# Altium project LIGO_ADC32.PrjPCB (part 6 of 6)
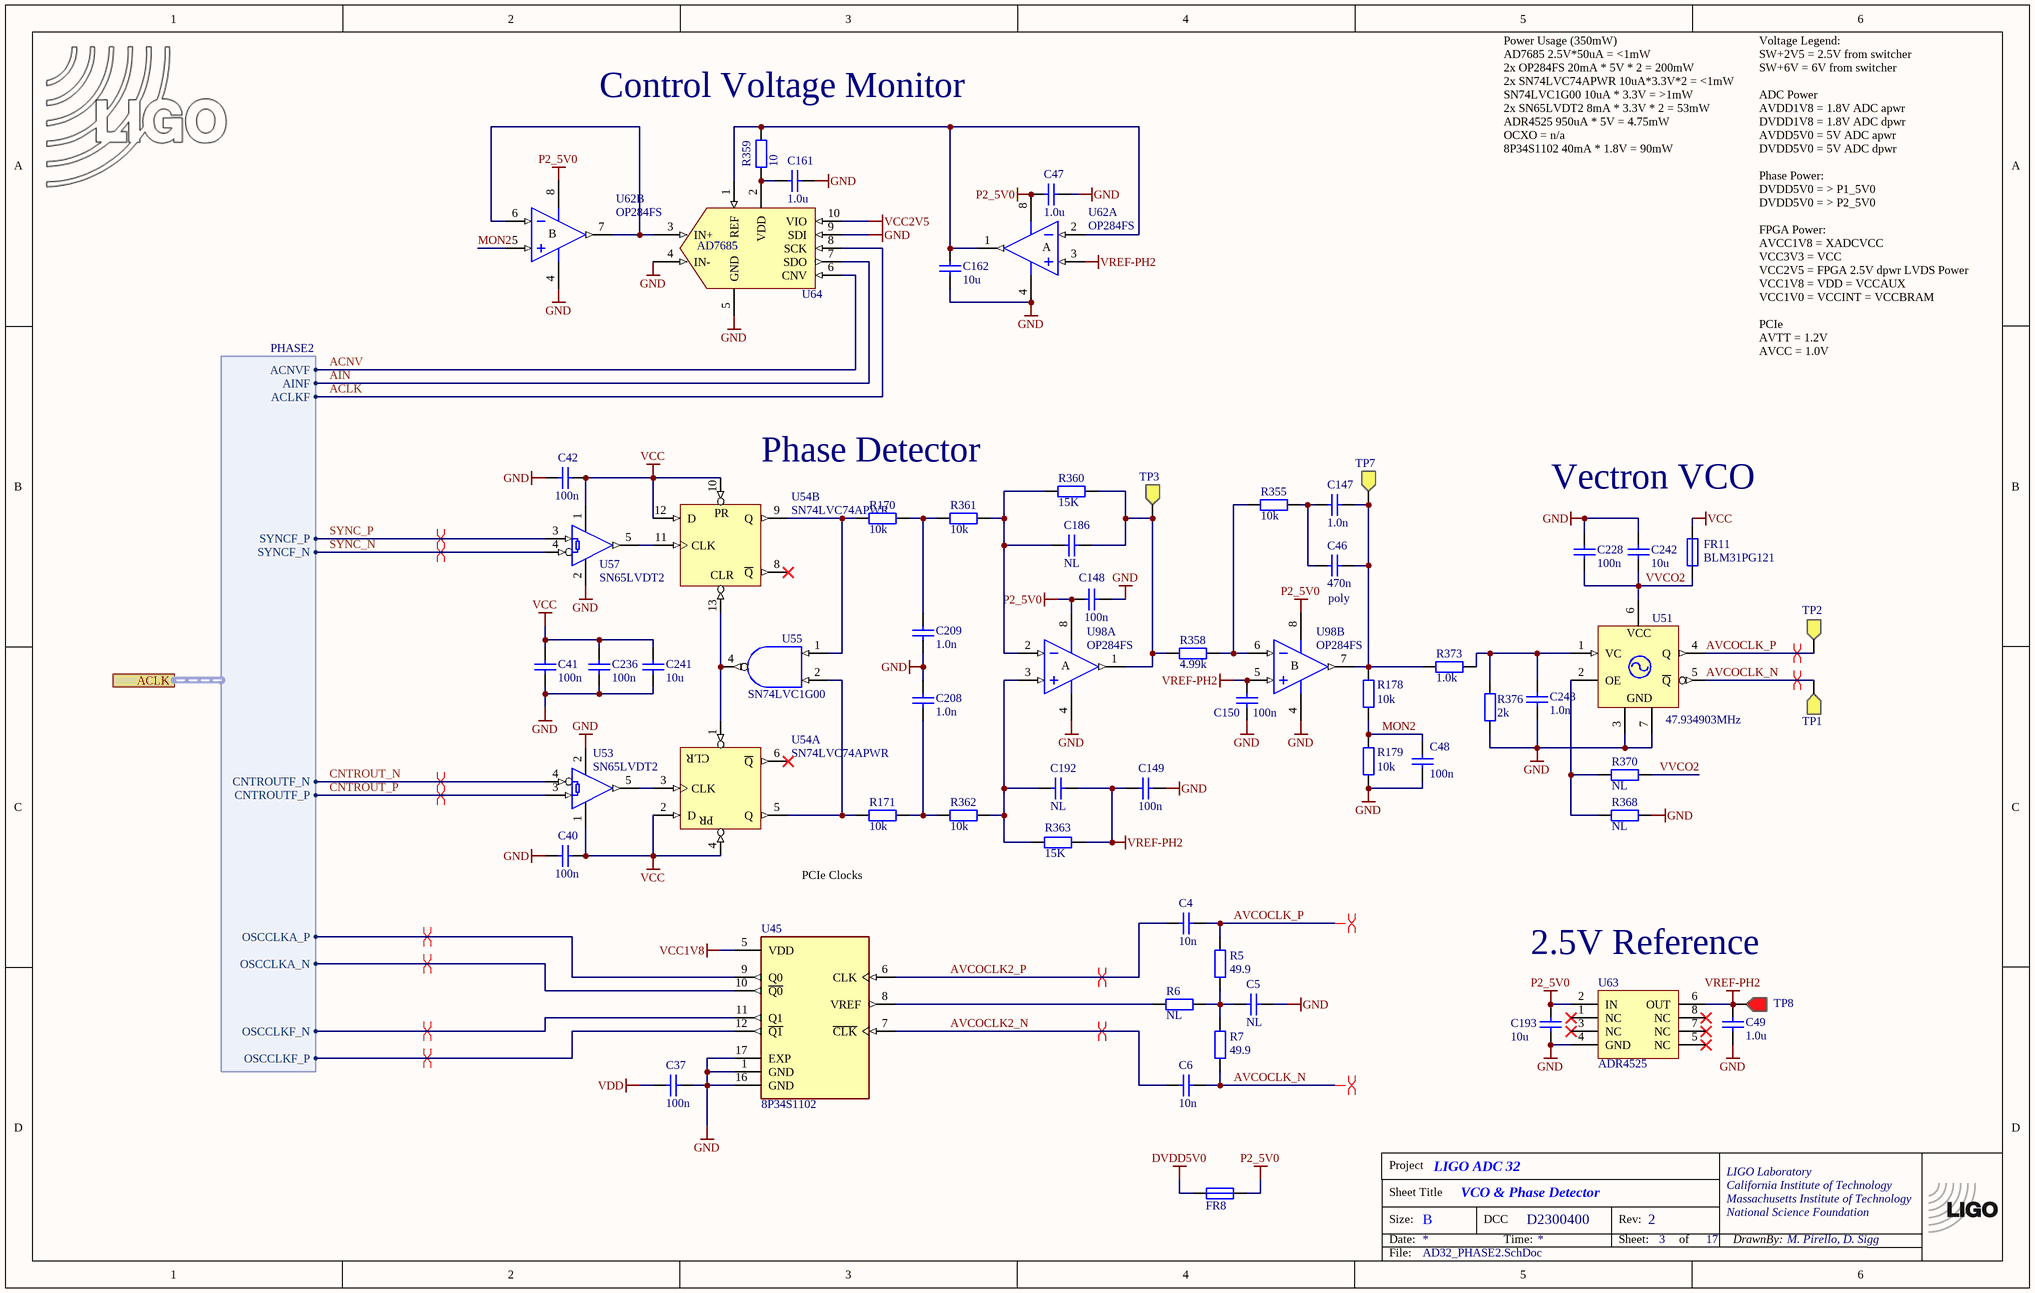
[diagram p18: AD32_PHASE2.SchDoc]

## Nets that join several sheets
12V: AD32_XADC (C110.1 R303.1 U94.8), AD32_PCIE_HL (5 pins)
12VA: AD32_PCIE_HL (FL2.2), AD32_Bipolar1 (FR5.1 TP39.1), AD32_Bipolar2 (FR6.1)
12VF: AD32_PCIE_HL (FL1.2), AD32_PowerFPGA (C111.1 R298.2)
+15V: Analog/ADC1/FrontEnd (20 pins), Analog/ADC2/FrontEnd (20 pins), Analog/ADC3/FrontEnd (20 pins), Analog/ADC4/FrontEnd (20 pins), Analog/ADC5/FrontEnd (20 pins), Analog/ADC6/FrontEnd (20 pins), Analog/ADC7/FrontEnd (20 pins), Analog/ADC8/FrontEnd (20 pins), AD32_XADC (C63.2 R202.1 U76.8), AD32_Bipolar1 (C129.2 D9.2 R327.1 TP17.1)
-15V: Analog/ADC1/FrontEnd (20 pins), Analog/ADC2/FrontEnd (20 pins), Analog/ADC3/FrontEnd (20 pins), Analog/ADC4/FrontEnd (20 pins), Analog/ADC5/FrontEnd (20 pins), Analog/ADC6/FrontEnd (20 pins), Analog/ADC7/FrontEnd (20 pins), Analog/ADC8/FrontEnd (20 pins), AD32_XADC (5 pins), AD32_Bipolar1 (C128.1 D10.1 R326.1 TP16.1)
AGND: ADC_TOP (12 pins), AD32_Inputs (10 pins), Analog/ADC1/FrontEnd (24 pins), Analog/ADC2/FrontEnd (24 pins), Analog/ADC3/FrontEnd (24 pins), Analog/ADC4/FrontEnd (24 pins), Analog/ADC5/FrontEnd (24 pins), Analog/ADC6/FrontEnd (24 pins), Analog/ADC7/FrontEnd (24 pins), Analog/ADC8/FrontEnd (24 pins), AD32_XADC (C63.1 C67.1 C145.1 U76.5), AD32_Power (20 pins), AD32_Bipolar1 (22 pins), AD32_Linear1 (35 pins), AD32_Bipolar2 (C108.1 C109.2 W2.2)
AVCC: FPGA_ARTIX7 (5 pins), AD32_PCIE_HL (11 pins)
AVCC1V8: AD32_XADC (C155.1 FR9.1), AD32_PowerFPGA (C64.2 R215.2 TP11.1 U77.7)
AVDD1V8: Analog/ADC1 (C289A.1 U34A.21), Analog/ADC2 (C289B.1 U34B.21), Analog/ADC3 (C289C.1 U34C.21), Analog/ADC4 (C289D.1 U34D.21), Analog/ADC5 (C289E.1 U34E.21), Analog/ADC6 (C289F.1 U34F.21), Analog/ADC7 (C289G.1 U34G.21), Analog/ADC8 (C289H.1 U34H.21), AD32_Linear1 (R223.1 R350.2 R351.1 TP21.1)
AVDD5V0: AD32_Inputs (C512.1 D2.2 R2.2 U133.8), Analog/ADC1 (C288A.1 C352A.1 C361A.1 U34A.26), Analog/ADC2 (C288B.1 C352B.1 C361B.1 U34B.26), Analog/ADC3 (C288C.1 C352C.1 C361C.1 U34C.26), Analog/ADC4 (C288D.1 C352D.1 C361D.1 U34D.26), Analog/ADC5 (C288E.1 C352E.1 C361E.1 U34E.26), Analog/ADC6 (C288F.1 C352F.1 C361F.1 U34F.26), Analog/ADC7 (C288G.1 C352G.1 C361G.1 U34G.26), Analog/ADC8 (C288H.1 C352H.1 C361H.1 U34H.26), AD32_Linear1 (6 pins)
AVTT: FPGA_ARTIX7 (7 pins), AD32_PCIE_HL (11 pins)
BUS3.3V: AD32_PCIE_HL (C287.1 R397.2 U99.6), AD32_PCIE (P2.A9 P2.A10 P2.B8)
BUS12V: AD32_PCIE_HL (D4.1), AD32_PCIE (5 pins)
DVDD1V8: Analog/ADC1 (5 pins), Analog/ADC2 (5 pins), Analog/ADC3 (5 pins), Analog/ADC4 (5 pins), Analog/ADC5 (5 pins), Analog/ADC6 (5 pins), Analog/ADC7 (5 pins), Analog/ADC8 (5 pins), AD32_Linear1 (R221.1 R348.2 R349.1 TP20.1)
DVDD5V0: Analog/ADC1 (C312A.1 C328A.1 C336A.1 U34A.25), Analog/ADC2 (C312B.1 C328B.1 C336B.1 U34B.25), Analog/ADC3 (C312C.1 C328C.1 C336C.1 U34C.25), Analog/ADC4 (C312D.1 C328D.1 C336D.1 U34D.25), Analog/ADC5 (C312E.1 C328E.1 C336E.1 U34E.25), Analog/ADC6 (C312F.1 C328F.1 C336F.1 U34F.25), Analog/ADC7 (C312G.1 C328G.1 C336G.1 U34G.25), Analog/ADC8 (C312H.1 C328H.1 C336H.1 U34H.25), AD32_PHASE (FR1.2), AD32_Linear1 (6 pins), AD32_PHASE2 (FR8.2)
EXTGND: AD32_PCIE_HL (6 pins), AD32_PCIE (21 pins)
GND: ADC_TOP (14 pins), AD32_Inputs (7 pins), Analog/ADC1 (34 pins), Analog/ADC2 (34 pins), Analog/ADC3 (34 pins), Analog/ADC4 (34 pins), Analog/ADC5 (34 pins), Analog/ADC6 (34 pins), Analog/ADC7 (34 pins), Analog/ADC8 (34 pins), AD32_FPGA (78 pins), FPGA_ARTIX7 (88 pins), AD32_XADC (5 pins), AD32_FLASH (28 pins), AD32_PHASE (38 pins), AD32_PCIE_HL (39 pins), AD32_Bipolar1 (19 pins), AD32_Bipolar2 (18 pins), AD32_PowerFPGA (45 pins), AD32_PHASE2 (39 pins)
SW+2V5: AD32_PCIE_HL (L9.1 L10.1), AD32_Linear1 (R261.2 R262.2 R263.2 R264.2), AD32_Bipolar2 (R301.1)
SW+6V: AD32_Linear1 (R265.2 R266.2), AD32_Bipolar2 (R302.1)
VCC: ADC_TOP (8 pins), AD32_XADC (12 pins), AD32_FLASH (C55.2 R194.1 U70.8), AD32_PHASE (16 pins), AD32_PowerFPGA (R210.1 R345.2 TP10.1), AD32_PHASE2 (14 pins)
VCC1V0: AD32_FPGA (23 pins), FPGA_ARTIX7 (17 pins), AD32_XADC (U92.2), AD32_PowerFPGA (R243.1 R344.2 TP28.1)
VCC1V8: AD32_Inputs (7 pins), Analog/ADC1 (8 pins), Analog/ADC2 (8 pins), Analog/ADC3 (8 pins), Analog/ADC4 (8 pins), Analog/ADC5 (8 pins), Analog/ADC6 (8 pins), Analog/ADC7 (8 pins), Analog/ADC8 (8 pins), AD32_FPGA (39 pins), FPGA_ARTIX7 (30 pins), AD32_XADC (U78.2), AD32_FLASH (19 pins), AD32_PHASE (U67.10), AD32_PCIE_HL (C269.1 U99.1), AD32_PowerFPGA (R260.1 R337.2 TP30.1), AD32_PHASE2 (C37.2 U45.5)
VCC2V5: AD32_Inputs (U42.1), AD32_FPGA (21 pins), FPGA_ARTIX7 (12 pins), AD32_XADC (FR2.2 U73.2), AD32_FLASH (R195.1), AD32_PowerFPGA (C140.2 R211.1 TP12.1 U77.8), AD32_PHASE2 (U64.10)
VREG: AD32_XADC (FR4.1), AD32_PowerFPGA (7 pins)
XADCGND: AD32_FPGA (C205.1), FPGA_ARTIX7 (U50.K9), AD32_XADC (37 pins)
XADCVCC: AD32_FPGA (C205.2), FPGA_ARTIX7 (U50.K10), AD32_XADC (C154.1 C158.1 FR9.2 U97.1)
ACLK1: AD32_Inputs (U100.3), Analog/ADC1 (U34A.45)
ACLK2: AD32_Inputs (U100.13), Analog/ADC2 (U34B.45)
ACLK3: AD32_Inputs (U100.15), Analog/ADC3 (U34C.45)
ACLK4: AD32_Inputs (U100.16), Analog/ADC4 (U34D.45)
ACLK5: AD32_Inputs (U100.9), Analog/ADC5 (U34E.45)
ACLK6: AD32_Inputs (U100.11), Analog/ADC6 (U34F.45)
ACLK7: AD32_Inputs (U100.6), Analog/ADC7 (U34G.45)
ACLK8: AD32_Inputs (U100.8), Analog/ADC8 (U34H.45)
ACLK.ACLKF: FPGA_ARTIX7 (U50.AA6), AD32_PHASE2 (U64.8)
ACLK.ACNVF: FPGA_ARTIX7 (U50.AA4), AD32_PHASE2 (U64.6)
ACLK.AINF: FPGA_ARTIX7 (U50.AB5), AD32_PHASE2 (U64.7)
ACLK.CNTROUTF_N: FPGA_ARTIX7 (U50.AA8), AD32_PHASE2 (U53.4)
ACLK.CNTROUTF_P: FPGA_ARTIX7 (U50.AB8), AD32_PHASE2 (U53.3)
ACLK.OSCCLKA_N: AD32_Inputs (U42.3), AD32_PHASE2 (U45.10)
ACLK.OSCCLKA_P: AD32_Inputs (U42.4), AD32_PHASE2 (U45.9)
ACLK.OSCCLKF_N: FPGA_ARTIX7 (U50.V4), AD32_PHASE2 (U45.11)
ACLK.OSCCLKF_P: FPGA_ARTIX7 (U50.W4), AD32_PHASE2 (U45.12)
ACLK.SYNCF_N: FPGA_ARTIX7 (U50.AB6), AD32_PHASE2 (U57.4)
ACLK.SYNCF_P: FPGA_ARTIX7 (U50.AB7), AD32_PHASE2 (U57.3)
ADC.CS: Analog/ADC1 (R401A.1 U34A.1), FPGA_ARTIX7 (U50.AB13)
ADC.CS: Analog/ADC2 (R401B.1 U34B.1), FPGA_ARTIX7 (U50.W16)
ADC.CS: Analog/ADC3 (R401C.1 U34C.1), FPGA_ARTIX7 (U50.W22)
ADC.CS: Analog/ADC4 (R401D.1 U34D.1), FPGA_ARTIX7 (U50.L18)
ADC.CS: Analog/ADC5 (R401E.1 U34E.1), FPGA_ARTIX7 (U50.J19)
ADC.CS: Analog/ADC6 (R401F.1 U34F.1), FPGA_ARTIX7 (U50.B21)
ADC.CS: Analog/ADC7 (R401G.1 U34G.1), FPGA_ARTIX7 (U50.B16)
ADC.CS: Analog/ADC8 (R401H.1 U34H.1), FPGA_ARTIX7 (U50.E13)
ADC.D0: Analog/ADC1 (U34A.10), FPGA_ARTIX7 (U50.W12)
ADC.D0: Analog/ADC2 (U34B.10), FPGA_ARTIX7 (U50.AA15)
ADC.D0: Analog/ADC3 (U34C.10), FPGA_ARTIX7 (U50.W20)
ADC.D0: Analog/ADC4 (U34D.10), FPGA_ARTIX7 (U50.N19)
ADC.D0: Analog/ADC5 (U34E.10), FPGA_ARTIX7 (U50.K22)
ADC.D0: Analog/ADC6 (U34F.10), FPGA_ARTIX7 (U50.E21)
ADC.D0: Analog/ADC7 (U34G.10), FPGA_ARTIX7 (U50.D20)
ADC.D0: Analog/ADC8 (U34H.10), FPGA_ARTIX7 (U50.A14)
ADC.D1: Analog/ADC1 (U34A.9), FPGA_ARTIX7 (U50.AA9)
ADC.D1: Analog/ADC2 (U34B.9), FPGA_ARTIX7 (U50.AB15)
ADC.D1: Analog/ADC3 (U34C.9), FPGA_ARTIX7 (U50.AB21)
ADC.D1: Analog/ADC4 (U34D.9), FPGA_ARTIX7 (U50.M18)
ADC.D1: Analog/ADC5 (U34E.9), FPGA_ARTIX7 (U50.K21)
ADC.D1: Analog/ADC6 (U34F.9), FPGA_ARTIX7 (U50.D22)
ADC.D1: Analog/ADC7 (U34G.9), FPGA_ARTIX7 (U50.A19)
ADC.D1: Analog/ADC8 (U34H.9), FPGA_ARTIX7 (U50.C14)
ADC.D2: Analog/ADC1 (U34A.8), FPGA_ARTIX7 (U50.Y11)
ADC.D2: Analog/ADC2 (U34B.8), FPGA_ARTIX7 (U50.AA16)
ADC.D2: Analog/ADC3 (U34C.8), FPGA_ARTIX7 (U50.AB22)
ADC.D2: Analog/ADC4 (U34D.8), FPGA_ARTIX7 (U50.N20)
ADC.D2: Analog/ADC5 (U34E.8), FPGA_ARTIX7 (U50.J22)
ADC.D2: Analog/ADC6 (U34F.8), FPGA_ARTIX7 (U50.D21)
ADC.D2: Analog/ADC7 (U34G.8), FPGA_ARTIX7 (U50.C19)
ADC.D2: Analog/ADC8 (U34H.8), FPGA_ARTIX7 (U50.A13)
ADC.D3: Analog/ADC1 (U34A.7), FPGA_ARTIX7 (U50.AA11)
ADC.D3: Analog/ADC2 (U34B.7), FPGA_ARTIX7 (U50.AB16)
ADC.D3: Analog/ADC3 (U34C.7), FPGA_ARTIX7 (U50.AA21)
ADC.D3: Analog/ADC4 (U34D.7), FPGA_ARTIX7 (U50.M20)
ADC.D3: Analog/ADC5 (U34E.7), FPGA_ARTIX7 (U50.J21)
ADC.D3: Analog/ADC6 (U34F.7), FPGA_ARTIX7 (U50.C22)
ADC.D3: Analog/ADC7 (U34G.7), FPGA_ARTIX7 (U50.A18)
ADC.D3: Analog/ADC8 (U34H.7), FPGA_ARTIX7 (U50.B13)
ADC.DCLK: Analog/ADC1 (U34A.11), FPGA_ARTIX7 (U50.W10)
ADC.DCLK: Analog/ADC2 (U34B.11), FPGA_ARTIX7 (U50.AA14)
ADC.DCLK: Analog/ADC3 (U34C.11), FPGA_ARTIX7 (U50.AB20)
ADC.DCLK: Analog/ADC4 (U34D.11), FPGA_ARTIX7 (U50.N18)
ADC.DCLK: Analog/ADC5 (U34E.11), FPGA_ARTIX7 (U50.L20)
ADC.DCLK: Analog/ADC6 (U34F.11), FPGA_ARTIX7 (U50.E22)
ADC.DCLK: Analog/ADC7 (U34G.11), FPGA_ARTIX7 (U50.A20)
ADC.DCLK: Analog/ADC8 (U34H.11), FPGA_ARTIX7 (U50.B15)
ADC.GPIO7: Analog/ADC1 (U34A.18), FPGA_ARTIX7 (U50.J17)
ADC.GPIO7: Analog/ADC2 (U34B.18), FPGA_ARTIX7 (U50.H18)
ADC.GPIO7: Analog/ADC3 (U34C.18), FPGA_ARTIX7 (U50.H19)
ADC.GPIO7: Analog/ADC4 (U34D.18), FPGA_ARTIX7 (U50.H17)
ADC.GPIO7: Analog/ADC5 (U34E.18), FPGA_ARTIX7 (U50.J16)
ADC.GPIO7: Analog/ADC6 (U34F.18), FPGA_ARTIX7 (U50.J15)
ADC.GPIO7: Analog/ADC7 (U34G.18), FPGA_ARTIX7 (U50.G16)
ADC.GPIO7: Analog/ADC8 (U34H.18), FPGA_ARTIX7 (U50.H15)
ADC.ODR: Analog/ADC1 (U34A.12), FPGA_ARTIX7 (U50.V10)
ADC.ODR: Analog/ADC2 (U34B.12), FPGA_ARTIX7 (U50.Y14)
ADC.ODR: Analog/ADC3 (U34C.12), FPGA_ARTIX7 (U50.AA20)
ADC.ODR: Analog/ADC4 (U34D.12), FPGA_ARTIX7 (U50.M17)
ADC.ODR: Analog/ADC5 (U34E.12), FPGA_ARTIX7 (U50.L21)
ADC.ODR: Analog/ADC6 (U34F.12), FPGA_ARTIX7 (U50.F21)
ADC.ODR: Analog/ADC7 (U34G.12), FPGA_ARTIX7 (U50.B20)
ADC.ODR: Analog/ADC8 (U34H.12), FPGA_ARTIX7 (U50.A15)
ADC.RST: Analog/ADC1 (R473A.1 U34A.54), Analog/ADC2 (R473B.1 U34B.54), Analog/ADC3 (R473C.1 U34C.54), Analog/ADC4 (R473D.1 U34D.54), Analog/ADC5 (R473E.1 U34E.54), Analog/ADC6 (R473F.1 U34F.54), Analog/ADC7 (R473G.1 U34G.54), Analog/ADC8 (R473H.1 U34H.54), FPGA_ARTIX7 (U50.V14)
ADC.SCLK: Analog/ADC1 (R417A.1 U34A.2), FPGA_ARTIX7 (U50.Y13)
ADC.SCLK: Analog/ADC2 (R417B.1 U34B.2), FPGA_ARTIX7 (U50.Y16)
ADC.SCLK: Analog/ADC3 (R417C.1 U34C.2), FPGA_ARTIX7 (U50.W21)
ADC.SCLK: Analog/ADC4 (R417D.1 U34D.2), FPGA_ARTIX7 (U50.M22)
ADC.SCLK: Analog/ADC5 (R417E.1 U34E.2), FPGA_ARTIX7 (U50.J20)
ADC.SCLK: Analog/ADC6 (R417F.1 U34F.2), FPGA_ARTIX7 (U50.A21)
ADC.SCLK: Analog/ADC7 (R417G.1 U34G.2), FPGA_ARTIX7 (U50.A16)
ADC.SCLK: Analog/ADC8 (R417H.1 U34H.2), FPGA_ARTIX7 (U50.D14)
ADC.SI: Analog/ADC1 (U34A.4), FPGA_ARTIX7 (U50.AA13)
ADC.SI: Analog/ADC2 (U34B.4), FPGA_ARTIX7 (U50.AB17)
ADC.SI: Analog/ADC3 (U34C.4), FPGA_ARTIX7 (U50.Y21)
ADC.SI: Analog/ADC4 (U34D.4), FPGA_ARTIX7 (U50.N22)
ADC.SI: Analog/ADC5 (U34E.4), FPGA_ARTIX7 (U50.H22)
ADC.SI: Analog/ADC6 (U34F.4), FPGA_ARTIX7 (U50.B22)
ADC.SI: Analog/ADC7 (U34G.4), FPGA_ARTIX7 (U50.B18)
ADC.SI: Analog/ADC8 (U34H.4), FPGA_ARTIX7 (U50.C13)
ADC.SO: Analog/ADC1 (U34A.3), FPGA_ARTIX7 (U50.AB12)
ADC.SO: Analog/ADC2 (U34B.3), FPGA_ARTIX7 (U50.Y17)
ADC.SO: Analog/ADC3 (U34C.3), FPGA_ARTIX7 (U50.Y22)
ADC.SO: Analog/ADC4 (U34D.3), FPGA_ARTIX7 (U50.M21)
ADC.SO: Analog/ADC5 (U34E.3), FPGA_ARTIX7 (U50.H20)
ADC.SO: Analog/ADC6 (U34F.3), FPGA_ARTIX7 (U50.C20)
ADC.SO: Analog/ADC7 (U34G.3), FPGA_ARTIX7 (U50.B17)
ADC.SO: Analog/ADC8 (U34H.3), FPGA_ARTIX7 (U50.C15)
ANALOG1.A1_N: ADC_TOP (P1.80), Analog/ADC1/FrontEnd (R618A.1 U125A.5)
ANALOG1.A1_P: ADC_TOP (P1.79), Analog/ADC1/FrontEnd (R634A.2 U125A.3)
ANALOG1.A2_N: ADC_TOP (P1.78), Analog/ADC1/FrontEnd (R554A.1 U102A.5)
ANALOG1.A2_P: ADC_TOP (P1.77), Analog/ADC1/FrontEnd (R569A.2 U102A.3)
ANALOG1.A3_N: ADC_TOP (P1.76), Analog/ADC1/FrontEnd (R617A.1 U117A.5)
ANALOG1.A3_P: ADC_TOP (P1.75), Analog/ADC1/FrontEnd (R633A.2 U117A.3)
ANALOG1.A4_N: ADC_TOP (P1.74), Analog/ADC1/FrontEnd (R553A.1 U101A.5)
ANALOG1.A4_P: ADC_TOP (P1.73), Analog/ADC1/FrontEnd (R577A.2 U101A.3)
ANALOG1.A5_N: ADC_TOP (P1.72), Analog/ADC2/FrontEnd (R618B.1 U125B.5)
ANALOG1.A5_P: ADC_TOP (P1.71), Analog/ADC2/FrontEnd (R634B.2 U125B.3)
ANALOG1.A6_N: ADC_TOP (P1.70), Analog/ADC2/FrontEnd (R554B.1 U102B.5)
ANALOG1.A6_P: ADC_TOP (P1.69), Analog/ADC2/FrontEnd (R569B.2 U102B.3)
ANALOG1.A7_N: ADC_TOP (P1.68), Analog/ADC2/FrontEnd (R617B.1 U117B.5)
ANALOG1.A7_P: ADC_TOP (P1.67), Analog/ADC2/FrontEnd (R633B.2 U117B.3)
ANALOG1.A8_N: ADC_TOP (P1.66), Analog/ADC2/FrontEnd (R553B.1 U101B.5)
ANALOG1.A8_P: ADC_TOP (P1.65), Analog/ADC2/FrontEnd (R577B.2 U101B.3)
ANALOG2.A1_N: ADC_TOP (P1.62), Analog/ADC3/FrontEnd (R618C.1 U125C.5)
ANALOG2.A1_P: ADC_TOP (P1.61), Analog/ADC3/FrontEnd (R634C.2 U125C.3)
ANALOG2.A2_N: ADC_TOP (P1.60), Analog/ADC3/FrontEnd (R554C.1 U102C.5)
ANALOG2.A2_P: ADC_TOP (P1.59), Analog/ADC3/FrontEnd (R569C.2 U102C.3)
ANALOG2.A3_N: ADC_TOP (P1.58), Analog/ADC3/FrontEnd (R617C.1 U117C.5)
ANALOG2.A3_P: ADC_TOP (P1.57), Analog/ADC3/FrontEnd (R633C.2 U117C.3)
ANALOG2.A4_N: ADC_TOP (P1.56), Analog/ADC3/FrontEnd (R553C.1 U101C.5)
ANALOG2.A4_P: ADC_TOP (P1.55), Analog/ADC3/FrontEnd (R577C.2 U101C.3)
ANALOG2.A5_N: ADC_TOP (P1.54), Analog/ADC4/FrontEnd (R618D.1 U125D.5)
ANALOG2.A5_P: ADC_TOP (P1.53), Analog/ADC4/FrontEnd (R634D.2 U125D.3)
ANALOG2.A6_N: ADC_TOP (P1.52), Analog/ADC4/FrontEnd (R554D.1 U102D.5)
ANALOG2.A6_P: ADC_TOP (P1.51), Analog/ADC4/FrontEnd (R569D.2 U102D.3)
ANALOG2.A7_N: ADC_TOP (P1.50), Analog/ADC4/FrontEnd (R617D.1 U117D.5)
ANALOG2.A7_P: ADC_TOP (P1.49), Analog/ADC4/FrontEnd (R633D.2 U117D.3)
ANALOG2.A8_N: ADC_TOP (P1.48), Analog/ADC4/FrontEnd (R553D.1 U101D.5)
ANALOG2.A8_P: ADC_TOP (P1.47), Analog/ADC4/FrontEnd (R577D.2 U101D.3)
ANALOG3.A1_N: ADC_TOP (P1.44), Analog/ADC5/FrontEnd (R618E.1 U125E.5)
ANALOG3.A1_P: ADC_TOP (P1.43), Analog/ADC5/FrontEnd (R634E.2 U125E.3)
ANALOG3.A2_N: ADC_TOP (P1.42), Analog/ADC5/FrontEnd (R554E.1 U102E.5)
ANALOG3.A2_P: ADC_TOP (P1.41), Analog/ADC5/FrontEnd (R569E.2 U102E.3)
ANALOG3.A3_N: ADC_TOP (P1.40), Analog/ADC5/FrontEnd (R617E.1 U117E.5)
ANALOG3.A3_P: ADC_TOP (P1.39), Analog/ADC5/FrontEnd (R633E.2 U117E.3)
ANALOG3.A4_N: ADC_TOP (P1.38), Analog/ADC5/FrontEnd (R553E.1 U101E.5)
ANALOG3.A4_P: ADC_TOP (P1.37), Analog/ADC5/FrontEnd (R577E.2 U101E.3)
ANALOG3.A5_N: ADC_TOP (P1.36), Analog/ADC6/FrontEnd (R618F.1 U125F.5)
ANALOG3.A5_P: ADC_TOP (P1.35), Analog/ADC6/FrontEnd (R634F.2 U125F.3)
ANALOG3.A6_N: ADC_TOP (P1.34), Analog/ADC6/FrontEnd (R554F.1 U102F.5)
ANALOG3.A6_P: ADC_TOP (P1.33), Analog/ADC6/FrontEnd (R569F.2 U102F.3)
ANALOG3.A7_N: ADC_TOP (P1.32), Analog/ADC6/FrontEnd (R617F.1 U117F.5)
ANALOG3.A7_P: ADC_TOP (P1.31), Analog/ADC6/FrontEnd (R633F.2 U117F.3)
ANALOG3.A8_N: ADC_TOP (P1.30), Analog/ADC6/FrontEnd (R553F.1 U101F.5)
ANALOG3.A8_P: ADC_TOP (P1.29), Analog/ADC6/FrontEnd (R577F.2 U101F.3)
ANALOG4.A1_N: ADC_TOP (P1.26), Analog/ADC7/FrontEnd (R618G.1 U125G.5)
ANALOG4.A1_P: ADC_TOP (P1.25), Analog/ADC7/FrontEnd (R634G.2 U125G.3)
ANALOG4.A2_N: ADC_TOP (P1.24), Analog/ADC7/FrontEnd (R554G.1 U102G.5)
ANALOG4.A2_P: ADC_TOP (P1.23), Analog/ADC7/FrontEnd (R569G.2 U102G.3)
ANALOG4.A3_N: ADC_TOP (P1.22), Analog/ADC7/FrontEnd (R617G.1 U117G.5)
ANALOG4.A3_P: ADC_TOP (P1.21), Analog/ADC7/FrontEnd (R633G.2 U117G.3)
ANALOG4.A4_N: ADC_TOP (P1.20), Analog/ADC7/FrontEnd (R553G.1 U101G.5)
ANALOG4.A4_P: ADC_TOP (P1.19), Analog/ADC7/FrontEnd (R577G.2 U101G.3)
ANALOG4.A5_N: ADC_TOP (P1.18), Analog/ADC8/FrontEnd (R618H.1 U125H.5)
ANALOG4.A5_P: ADC_TOP (P1.17), Analog/ADC8/FrontEnd (R634H.2 U125H.3)
ANALOG4.A6_N: ADC_TOP (P1.16), Analog/ADC8/FrontEnd (R554H.1 U102H.5)
ANALOG4.A6_P: ADC_TOP (P1.15), Analog/ADC8/FrontEnd (R569H.2 U102H.3)
ANALOG4.A7_N: ADC_TOP (P1.14), Analog/ADC8/FrontEnd (R617H.1 U117H.5)
ANALOG4.A7_P: ADC_TOP (P1.13), Analog/ADC8/FrontEnd (R633H.2 U117H.3)
ANALOG4.A8_N: ADC_TOP (P1.12), Analog/ADC8/FrontEnd (R553H.1 U101H.5)
ANALOG4.A8_P: ADC_TOP (P1.11), Analog/ADC8/FrontEnd (R577H.2 U101H.3)
APWR1.SYNC_DIFF: FPGA_ARTIX7 (U50.Y3), AD32_Bipolar1 (R293.1 U95.19)
APWR2.SYNC_DUAL: FPGA_ARTIX7 (U50.AA1), AD32_Bipolar2 (R294.1 U96.19)
CLKE_N: ADC_TOP (R150.2 R156.2 U46.6), FPGA_ARTIX7 (U50.C17)
CLKE_P: ADC_TOP (R151.2 R156.1 U46.7), FPGA_ARTIX7 (U50.D17)
CLKO_N: ADC_TOP (R152.2 R157.2 U47.6), FPGA_ARTIX7 (U50.K19)
CLKO_P: ADC_TOP (R153.2 R157.1 U47.7), FPGA_ARTIX7 (U50.K18)
CLOCK.ACLK: FPGA_ARTIX7 (U50.C18), AD32_PHASE (U67.8)
CLOCK.ACNV: FPGA_ARTIX7 (U50.E16), AD32_PHASE (U67.6)
CLOCK.AIN: FPGA_ARTIX7 (U50.D16), AD32_PHASE (U67.7)
CLOCK.CNTROUT_N: FPGA_ARTIX7 (U50.D1), AD32_PHASE (U56.4)
CLOCK.CNTROUT_P: FPGA_ARTIX7 (U50.E1), AD32_PHASE (U56.3)
CLOCK.OSCCLK_N: FPGA_ARTIX7 (U50.G4), AD32_PHASE (R164.1 U52.7)
CLOCK.OSCCLK_P: FPGA_ARTIX7 (U50.H4), AD32_PHASE (R166.2 U52.6)
CLOCK.SYNC_N: FPGA_ARTIX7 (U50.F1), AD32_PHASE (U61.4)
CLOCK.SYNC_P: FPGA_ARTIX7 (U50.G1), AD32_PHASE (U61.3)
EXT.TRIGout_N: ADC_TOP (R148.1 R382.1 U48.2), FPGA_ARTIX7 (U50.H5)
EXT.TRIGout_P: ADC_TOP (R149.1 R382.2 U48.3), FPGA_ARTIX7 (U50.J5)
EXTCLK.CAUX_N: FPGA_ARTIX7 (U50.T4), AD32_FLASH (R188.2 U70.6)
EXTCLK.CAUX_P: FPGA_ARTIX7 (U50.R4), AD32_FLASH (R190.2 U70.7)
LED_A: AD32_FPGA (Q10.1 R399.1), FPGA_ARTIX7 (U50.R6)
LED_B: AD32_FPGA (Q9.1 R394.1), FPGA_ARTIX7 (U50.T6)
LED_C: AD32_FPGA (Q8.1 R389.1), FPGA_ARTIX7 (U50.T5)
LED_D: AD32_FPGA (Q7.1 R381.1), FPGA_ARTIX7 (U50.U3)
LED_PG: AD32_FPGA (Q6.1 R378.1), FPGA_ARTIX7 (U50.U5)
OUT1_N_ADC1: Analog/ADC1 (U34A.30), Analog/ADC1/FrontEnd (C3A.1 R20A.2)
OUT1_N_ADC2: Analog/ADC2 (U34B.30), Analog/ADC2/FrontEnd (C3B.1 R20B.2)
OUT1_N_ADC3: Analog/ADC3 (U34C.30), Analog/ADC3/FrontEnd (C3C.1 R20C.2)
OUT1_N_ADC4: Analog/ADC4 (U34D.30), Analog/ADC4/FrontEnd (C3D.1 R20D.2)
OUT1_N_ADC5: Analog/ADC5 (U34E.30), Analog/ADC5/FrontEnd (C3E.1 R20E.2)
OUT1_N_ADC6: Analog/ADC6 (U34F.30), Analog/ADC6/FrontEnd (C3F.1 R20F.2)
OUT1_N_ADC7: Analog/ADC7 (U34G.30), Analog/ADC7/FrontEnd (C3G.1 R20G.2)
OUT1_N_ADC8: Analog/ADC8 (U34H.30), Analog/ADC8/FrontEnd (C3H.1 R20H.2)
OUT1_P_ADC1: Analog/ADC1 (U34A.29), Analog/ADC1/FrontEnd (C3A.2 R36A.2)
OUT1_P_ADC2: Analog/ADC2 (U34B.29), Analog/ADC2/FrontEnd (C3B.2 R36B.2)
OUT1_P_ADC3: Analog/ADC3 (U34C.29), Analog/ADC3/FrontEnd (C3C.2 R36C.2)
OUT1_P_ADC4: Analog/ADC4 (U34D.29), Analog/ADC4/FrontEnd (C3D.2 R36D.2)
OUT1_P_ADC5: Analog/ADC5 (U34E.29), Analog/ADC5/FrontEnd (C3E.2 R36E.2)
OUT1_P_ADC6: Analog/ADC6 (U34F.29), Analog/ADC6/FrontEnd (C3F.2 R36F.2)
OUT1_P_ADC7: Analog/ADC7 (U34G.29), Analog/ADC7/FrontEnd (C3G.2 R36G.2)
OUT1_P_ADC8: Analog/ADC8 (U34H.29), Analog/ADC8/FrontEnd (C3H.2 R36H.2)
OUT2_N_ADC1: Analog/ADC1 (U34A.33), Analog/ADC1/FrontEnd (C19A.1 R84A.2)
OUT2_N_ADC2: Analog/ADC2 (U34B.33), Analog/ADC2/FrontEnd (C19B.1 R84B.2)
OUT2_N_ADC3: Analog/ADC3 (U34C.33), Analog/ADC3/FrontEnd (C19C.1 R84C.2)
OUT2_N_ADC4: Analog/ADC4 (U34D.33), Analog/ADC4/FrontEnd (C19D.1 R84D.2)
OUT2_N_ADC5: Analog/ADC5 (U34E.33), Analog/ADC5/FrontEnd (C19E.1 R84E.2)
OUT2_N_ADC6: Analog/ADC6 (U34F.33), Analog/ADC6/FrontEnd (C19F.1 R84F.2)
OUT2_N_ADC7: Analog/ADC7 (U34G.33), Analog/ADC7/FrontEnd (C19G.1 R84G.2)
OUT2_N_ADC8: Analog/ADC8 (U34H.33), Analog/ADC8/FrontEnd (C19H.1 R84H.2)
OUT2_P_ADC1: Analog/ADC1 (U34A.32), Analog/ADC1/FrontEnd (C19A.2 R100A.2)
OUT2_P_ADC2: Analog/ADC2 (U34B.32), Analog/ADC2/FrontEnd (C19B.2 R100B.2)
OUT2_P_ADC3: Analog/ADC3 (U34C.32), Analog/ADC3/FrontEnd (C19C.2 R100C.2)
OUT2_P_ADC4: Analog/ADC4 (U34D.32), Analog/ADC4/FrontEnd (C19D.2 R100D.2)
OUT2_P_ADC5: Analog/ADC5 (U34E.32), Analog/ADC5/FrontEnd (C19E.2 R100E.2)
OUT2_P_ADC6: Analog/ADC6 (U34F.32), Analog/ADC6/FrontEnd (C19F.2 R100F.2)
OUT2_P_ADC7: Analog/ADC7 (U34G.32), Analog/ADC7/FrontEnd (C19G.2 R100G.2)
OUT2_P_ADC8: Analog/ADC8 (U34H.32), Analog/ADC8/FrontEnd (C19H.2 R100H.2)
OUT3_N_ADC1: Analog/ADC1 (U34A.39), Analog/ADC1/FrontEnd (C11A.1 R28A.2)
OUT3_N_ADC2: Analog/ADC2 (U34B.39), Analog/ADC2/FrontEnd (C11B.1 R28B.2)
OUT3_N_ADC3: Analog/ADC3 (U34C.39), Analog/ADC3/FrontEnd (C11C.1 R28C.2)
OUT3_N_ADC4: Analog/ADC4 (U34D.39), Analog/ADC4/FrontEnd (C11D.1 R28D.2)
OUT3_N_ADC5: Analog/ADC5 (U34E.39), Analog/ADC5/FrontEnd (C11E.1 R28E.2)
OUT3_N_ADC6: Analog/ADC6 (U34F.39), Analog/ADC6/FrontEnd (C11F.1 R28F.2)
OUT3_N_ADC7: Analog/ADC7 (U34G.39), Analog/ADC7/FrontEnd (C11G.1 R28G.2)
OUT3_N_ADC8: Analog/ADC8 (U34H.39), Analog/ADC8/FrontEnd (C11H.1 R28H.2)
OUT3_P_ADC1: Analog/ADC1 (U34A.38), Analog/ADC1/FrontEnd (C11A.2 R44A.2)
OUT3_P_ADC2: Analog/ADC2 (U34B.38), Analog/ADC2/FrontEnd (C11B.2 R44B.2)
OUT3_P_ADC3: Analog/ADC3 (U34C.38), Analog/ADC3/FrontEnd (C11C.2 R44C.2)
OUT3_P_ADC4: Analog/ADC4 (U34D.38), Analog/ADC4/FrontEnd (C11D.2 R44D.2)
OUT3_P_ADC5: Analog/ADC5 (U34E.38), Analog/ADC5/FrontEnd (C11E.2 R44E.2)
OUT3_P_ADC6: Analog/ADC6 (U34F.38), Analog/ADC6/FrontEnd (C11F.2 R44F.2)
OUT3_P_ADC7: Analog/ADC7 (U34G.38), Analog/ADC7/FrontEnd (C11G.2 R44G.2)
OUT3_P_ADC8: Analog/ADC8 (U34H.38), Analog/ADC8/FrontEnd (C11H.2 R44H.2)
OUT4_N_ADC1: Analog/ADC1 (U34A.42), Analog/ADC1/FrontEnd (C27A.1 R92A.2)
OUT4_N_ADC2: Analog/ADC2 (U34B.42), Analog/ADC2/FrontEnd (C27B.1 R92B.2)
OUT4_N_ADC3: Analog/ADC3 (U34C.42), Analog/ADC3/FrontEnd (C27C.1 R92C.2)
OUT4_N_ADC4: Analog/ADC4 (U34D.42), Analog/ADC4/FrontEnd (C27D.1 R92D.2)
OUT4_N_ADC5: Analog/ADC5 (U34E.42), Analog/ADC5/FrontEnd (C27E.1 R92E.2)
OUT4_N_ADC6: Analog/ADC6 (U34F.42), Analog/ADC6/FrontEnd (C27F.1 R92F.2)
OUT4_N_ADC7: Analog/ADC7 (U34G.42), Analog/ADC7/FrontEnd (C27G.1 R92G.2)
OUT4_N_ADC8: Analog/ADC8 (U34H.42), Analog/ADC8/FrontEnd (C27H.1 R92H.2)
OUT4_P_ADC1: Analog/ADC1 (U34A.41), Analog/ADC1/FrontEnd (C27A.2 R108A.2)
OUT4_P_ADC2: Analog/ADC2 (U34B.41), Analog/ADC2/FrontEnd (C27B.2 R108B.2)
OUT4_P_ADC3: Analog/ADC3 (U34C.41), Analog/ADC3/FrontEnd (C27C.2 R108C.2)
OUT4_P_ADC4: Analog/ADC4 (U34D.41), Analog/ADC4/FrontEnd (C27D.2 R108D.2)
OUT4_P_ADC5: Analog/ADC5 (U34E.41), Analog/ADC5/FrontEnd (C27E.2 R108E.2)
OUT4_P_ADC6: Analog/ADC6 (U34F.41), Analog/ADC6/FrontEnd (C27F.2 R108F.2)
OUT4_P_ADC7: Analog/ADC7 (U34G.41), Analog/ADC7/FrontEnd (C27G.2 R108G.2)
OUT4_P_ADC8: Analog/ADC8 (U34H.41), Analog/ADC8/FrontEnd (C27H.2 R108H.2)
PCIE.PCIE_CLK_N: FPGA_ARTIX7 (U50.E6), AD32_PCIE_HL (C284.2)
PCIE.PCIE_CLK_P: FPGA_ARTIX7 (U50.F6), AD32_PCIE_HL (C286.2)
PCIE.PCIE_PERST: FPGA_ARTIX7 (U50.E14), AD32_PCIE_HL (U99.3)
PCIE.PCIE_PWRGD: FPGA_ARTIX7 (U50.R1), AD32_PCIE_HL (U83.5 U84.5)
PCIE.PCIE_RX0_N: FPGA_ARTIX7 (U50.B8), AD32_PCIE (P2.B15)
PCIE.PCIE_RX0_P: FPGA_ARTIX7 (U50.A8), AD32_PCIE (P2.B14)
PCIE.PCIE_RX1_N: FPGA_ARTIX7 (U50.D11), AD32_PCIE (P2.B20)
PCIE.PCIE_RX1_P: FPGA_ARTIX7 (U50.C11), AD32_PCIE (P2.B19)
PCIE.PCIE_RX2_N: FPGA_ARTIX7 (U50.B10), AD32_PCIE (P2.B24)
PCIE.PCIE_RX2_P: FPGA_ARTIX7 (U50.A10), AD32_PCIE (P2.B23)
PCIE.PCIE_RX3_N: FPGA_ARTIX7 (U50.D9), AD32_PCIE (P2.B28)
PCIE.PCIE_RX3_P: FPGA_ARTIX7 (U50.C9), AD32_PCIE (P2.B27)
PCIE.PCIE_TX0_N: FPGA_ARTIX7 (U50.B4), AD32_PCIE_HL (C281.2)
PCIE.PCIE_TX0_P: FPGA_ARTIX7 (U50.A4), AD32_PCIE_HL (C283.2)
PCIE.PCIE_TX1_N: FPGA_ARTIX7 (U50.D5), AD32_PCIE_HL (C279.2)
PCIE.PCIE_TX1_P: FPGA_ARTIX7 (U50.C5), AD32_PCIE_HL (C280.2)
PCIE.PCIE_TX2_N: FPGA_ARTIX7 (U50.B6), AD32_PCIE_HL (C277.2)
PCIE.PCIE_TX2_P: FPGA_ARTIX7 (U50.A6), AD32_PCIE_HL (C278.2)
PCIE.PCIE_TX3_N: FPGA_ARTIX7 (U50.D7), AD32_PCIE_HL (C273.2)
PCIE.PCIE_TX3_P: FPGA_ARTIX7 (U50.C7), AD32_PCIE_HL (C276.2)
PER0_N: AD32_PCIE_HL (C281.1), AD32_PCIE (P2.A17)
PER0_P: AD32_PCIE_HL (C283.1), AD32_PCIE (P2.A16)
PER1_N: AD32_PCIE_HL (C279.1), AD32_PCIE (P2.A22)
PER1_P: AD32_PCIE_HL (C280.1), AD32_PCIE (P2.A21)
PER2_N: AD32_PCIE_HL (C277.1), AD32_PCIE (P2.A26)
PER2_P: AD32_PCIE_HL (C278.1), AD32_PCIE (P2.A25)
PER3_N: AD32_PCIE_HL (C273.1), AD32_PCIE (P2.A30)
PER3_P: AD32_PCIE_HL (C276.1), AD32_PCIE (P2.A29)
PERST#: AD32_PCIE_HL (R396.1), AD32_PCIE (P2.A11)
POWER.PWRSYNC: FPGA_ARTIX7 (U50.AB1), AD32_PowerFPGA (R330.2 TP27.1)
REF0: AD32_Inputs (U133.6 U133.7), Analog/ADC1 (C383A.2 U34A.36), Analog/ADC2 (C383B.2 U34B.36), Analog/ADC3 (C383C.2 U34C.36), Analog/ADC4 (C383D.2 U34D.36)
REF1: AD32_Inputs (U133.1 U133.2), Analog/ADC5 (C383E.2 U34E.36), Analog/ADC6 (C383F.2 U34F.36), Analog/ADC7 (C383G.2 U34G.36), Analog/ADC8 (C383H.2 U34H.36)
REFCLK_N: AD32_PCIE_HL (C284.1), AD32_PCIE (P2.A14)
REFCLK_P: AD32_PCIE_HL (C286.1), AD32_PCIE (P2.A13)
SENSE.SENS_10_P: AD32_XADC (U92.3), AD32_PowerFPGA (C76.1 L3.2 R228.2 R243.2)
SENSE.SENS_18_P: AD32_XADC (U78.3), AD32_PowerFPGA (C77.2 L4.2 R226.2 R260.2)
SENSE.SENS_25_P: AD32_XADC (U73.3), AD32_PowerFPGA (C69.2 L2.2 R211.2 R218.2)
SENSE.SENS_33_P: AD32_XADC (U72.3), AD32_PowerFPGA (C68.2 L1.2 R210.2 R224.2)
SENSE.SENS_120b_N: AD32_XADC (R269.2), AD32_PCIE_HL (R271.2)
SENSE.SENS_120b_P: AD32_XADC (R272.2), AD32_PCIE_HL (R271.3)
SENSE.SENS_120x_N: AD32_XADC (R270.1), AD32_PCIE_HL (R296.3)
SENSE.SENS_120x_P: AD32_XADC (R297.1), AD32_PCIE_HL (R296.2)
SENSE.SENS_+15: AD32_XADC (R332.1), AD32_Bipolar1 (R252.2 U81.6 U82.6)
SENSE.SENS_-15_N: AD32_XADC (R325.1), AD32_Bipolar1 (R236.1 R237.1 R251.1 R326.2)
SENSE.SENS_AVCC: AD32_XADC (R334.1), AD32_PCIE_HL (R254.2 U84.6)
SENSE.SENS_AVDD1V8: AD32_XADC (R321.1), AD32_Linear1 (R248.1 U87.6 U88.6)
SENSE.SENS_AVDD5V0: AD32_XADC (R322.1), AD32_Linear1 (R249.1 U89.6)
SENSE.SENS_AVTT: AD32_XADC (R333.1), AD32_PCIE_HL (R253.2 U83.6)
SENSE.SENS_DVDD1V8: AD32_XADC (R320.1), AD32_Linear1 (R247.1 U85.6 U86.6)
SENSE.SENS_DVDD5V0: AD32_XADC (R323.1), AD32_Linear1 (R250.1 U90.6)
SQSPI.EMCLK_EN: FPGA_ARTIX7 (U50.U21), AD32_FLASH (R145.2 Y1.1)
SQSPI.PUDC_B: FPGA_ARTIX7 (U50.U22), AD32_FLASH (R139.1 R140.1)
SQSPI.QSPI_CS: FPGA_ARTIX7 (U50.T19), AD32_FLASH (R155.2 U43.7 U44.1)
SQSPI.QSPI_DQ0: FPGA_ARTIX7 (U50.P22), AD32_FLASH (R147.2)
SQSPI.QSPI_DQ1: FPGA_ARTIX7 (U50.R22), AD32_FLASH (R159.2)
SQSPI.QSPI_DQ2: FPGA_ARTIX7 (U50.P21), AD32_FLASH (R154.2)
SQSPI.QSPI_DQ3: FPGA_ARTIX7 (U50.R21), AD32_FLASH (R141.2)
SQSPI.QSPI_EMCLK: FPGA_ARTIX7 (U50.V22), AD32_FLASH (Y1.3)
VCOM: Analog/ADC1 (U34A.34), Analog/ADC1/FrontEnd (U2A.2 U3A.2 U18A.2 U19A.2)
VCOM: Analog/ADC2 (U34B.34), Analog/ADC2/FrontEnd (U2B.2 U3B.2 U18B.2 U19B.2)
VCOM: Analog/ADC3 (U34C.34), Analog/ADC3/FrontEnd (U2C.2 U3C.2 U18C.2 U19C.2)
VCOM: Analog/ADC4 (U34D.34), Analog/ADC4/FrontEnd (U2D.2 U3D.2 U18D.2 U19D.2)
VCOM: Analog/ADC5 (U34E.34), Analog/ADC5/FrontEnd (U2E.2 U3E.2 U18E.2 U19E.2)
VCOM: Analog/ADC6 (U34F.34), Analog/ADC6/FrontEnd (U2F.2 U3F.2 U18F.2 U19F.2)
VCOM: Analog/ADC7 (U34G.34), Analog/ADC7/FrontEnd (U2G.2 U3G.2 U18G.2 U19G.2)
VCOM: Analog/ADC8 (U34H.34), Analog/ADC8/FrontEnd (U2H.2 U3H.2 U18H.2 U19H.2)
XADC_N: AD32_XADC (C151.2 C204.1 R354.2), AD32_FLASH (U50.M9)
XADC_P: AD32_XADC (C151.1 C204.2 R353.2), AD32_FLASH (U50.L10)
XADC_REF_N: AD32_XADC (W3.2), AD32_FLASH (U50.L9)
XADC_REF_P: AD32_XADC (C163.1 R204.1 U97.2), AD32_FLASH (U50.M10)
XMUX0: FPGA_ARTIX7 (U50.K1), AD32_XADC (U68.12)
XMUX1: FPGA_ARTIX7 (U50.L1), AD32_XADC (U68.11)
XMUX2: FPGA_ARTIX7 (U50.M1), AD32_XADC (U68.10)
XMUX3: FPGA_ARTIX7 (U50.J1), AD32_XADC (U68.13)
